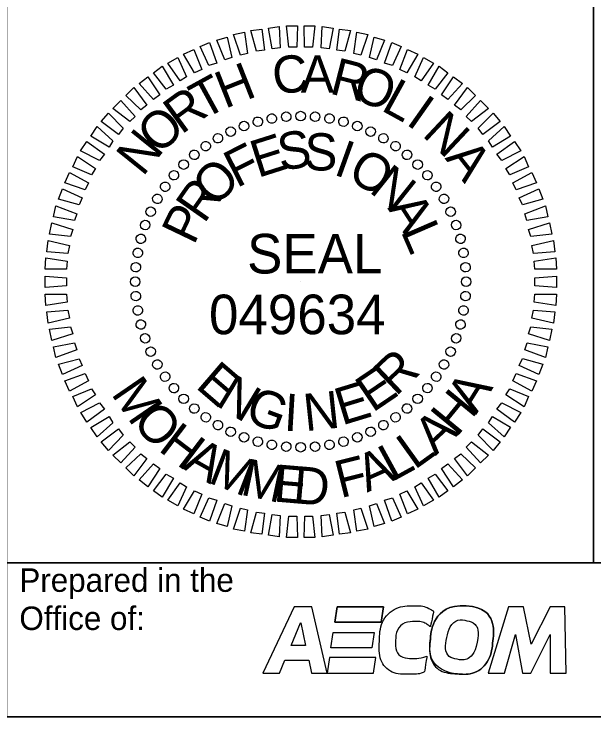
# Model space of a CAD drawing. Extents: x 270 to 1290, y -4845 to -4185.
# Drawn here: x 1150.7 to 1210, y -4305.5 to -4233.7 of the extents above; entities that cross this region are included whole.
import ezdxf

# ---------------------------------------------------------------- set-up
doc = ezdxf.new("R2010")
doc.units = 0
for name, color, linetype in [('Default', 7, 'Continuous'), ('Prop DSN Text', 7, 'Continuous'), ('Sheet Block Title CELL', 7, 'Continuous'), ('Sheet Border Standard 30in CELL', 7, 'Continuous'), ('Sheet Professional Seal CELL', 7, 'Continuous'), ('Sheet Sticker Exception Certification CELL', 7, 'Continuous')]:
    doc.layers.add(name, color=color, linetype=linetype)

# ---------------------------------------------------------------- blocks, each defined once
blk = doc.blocks.new('block 3')
at = {"layer": 'Default'}
blk.add_open_spline([(0.12275, 0.09393), (0.12554, 0.09373), (0.12726, 0.09146), (0.12695, 0.08843), (0.12663, 0.08531), (0.12411, 0.08298), (0.12127, 0.08318), (0.11848, 0.08338), (0.11676, 0.08565), (0.11707, 0.08868), (0.11739, 0.0918), (0.11991, 0.09413), (0.12275, 0.09393)], degree=3, dxfattribs=at)
blk = doc.blocks.new('block 2')
at = {"layer": 'Default'}
for p, q in [((0.10234, 0.09375), (0.10197, 0.09133)), ((0.10966, 0.09375), (0.10234, 0.09375)), ((0.10929, 0.09133), (0.10966, 0.09375)), ((0.10197, 0.09133), (0.10929, 0.09133)), ((0.10137, 0.08733), (0.10174, 0.08975)), ((0.10174, 0.08975), (0.10818, 0.08975)), ((0.10818, 0.08975), (0.10782, 0.08733)), ((0.10782, 0.08733), (0.10137, 0.08733)), ((0.10114, 0.08576), (0.10078, 0.08333)), ((0.10846, 0.08576), (0.10114, 0.08576)), ((0.1081, 0.08333), (0.10846, 0.08576)), ((0.10078, 0.08333), (0.1081, 0.08333))]:
    blk.add_line(p, q, dxfattribs=at)
for points in [[(0.10929, 0.09133), (0.10197, 0.09133), (0.10234, 0.09375), (0.10966, 0.09375), (0.10929, 0.09133)], [(0.10782, 0.08733), (0.10137, 0.08733), (0.10174, 0.08975), (0.10818, 0.08975), (0.10782, 0.08733)], [(0.10846, 0.08576), (0.10114, 0.08576), (0.10078, 0.08333), (0.1081, 0.08333), (0.10846, 0.08576)]]:
    blk.add_lwpolyline(points, dxfattribs=at)
blk = doc.blocks.new('POINT_DISPLAY')
at = {"layer": 'Default'}
blk.add_line((0, 0), (0, 0), dxfattribs=at)

msp = doc.modelspace()

# ---------------------------------------------------------------- linework, layer by layer
at = {"layer": 'Prop DSN Text'}
for p, q in [((1179.347, -4294.287), (1176.172, -4301.037)), ((1181.176, -4294.287), (1179.347, -4294.287)), ((1182.736, -4301.037), (1181.176, -4294.287)), ((1201.294, -4294.286), (1199.197, -4301.037)), ((1202.814, -4294.286), (1201.294, -4294.286)), ((1203.601, -4298.094), (1202.814, -4294.286)), ((1205.549, -4294.286), (1203.601, -4298.094)), ((1207.071, -4294.286), (1205.549, -4294.286)), ((1207.195, -4301.037), (1207.071, -4294.286)), ((1179.043, -4298.234), (1180.023, -4295.893)), ((1180.023, -4295.893), (1180.038, -4295.893)), ((1180.038, -4295.893), (1180.535, -4298.234)), ((1200.874, -4301.037), (1202.016, -4297.085)), ((1202.016, -4297.085), (1202.733, -4301.037)), ((1203.588, -4301.037), (1205.566, -4297.087)), ((1205.566, -4297.087), (1205.542, -4301.037)), ((1180.535, -4298.234), (1179.043, -4298.234)), ((1177.87, -4301.037), (1178.421, -4299.721)), ((1178.421, -4299.721), (1180.851, -4299.721)), ((1180.851, -4299.721), (1181.13, -4301.037)), ((1176.172, -4301.037), (1177.87, -4301.037)), ((1181.13, -4301.037), (1182.736, -4301.037)), ((1199.197, -4301.037), (1200.874, -4301.037)), ((1202.733, -4301.037), (1203.588, -4301.037)), ((1205.542, -4301.037), (1207.195, -4301.037))]:
    msp.add_line(p, q, dxfattribs=at)
for points in [[(1181.13, -4301.037), (1182.736, -4301.037), (1181.176, -4294.287), (1179.347, -4294.287), (1176.172, -4301.037), (1177.87, -4301.037), (1178.421, -4299.721), (1180.851, -4299.721), (1181.13, -4301.037)], [(1207.195, -4301.037), (1207.071, -4294.286), (1205.549, -4294.286), (1203.601, -4298.094), (1202.814, -4294.286), (1201.294, -4294.286), (1199.197, -4301.037), (1200.874, -4301.037), (1202.016, -4297.085), (1202.733, -4301.037), (1203.588, -4301.037), (1205.566, -4297.087), (1205.542, -4301.037), (1207.195, -4301.037)]]:
    msp.add_lwpolyline(points, dxfattribs=at)
for points in [[(1195.313, -4301.008), (1193.928, -4300.594), (1193.12, -4299.267), (1193.294, -4297.572), (1193.502, -4295.547), (1195.135, -4294.04), (1196.978, -4294.171)], [(1192.943, -4299.306), (1192.491, -4299.515), (1191.815, -4299.549), (1191.484, -4299.549), (1190.416, -4299.549), (1189.709, -4298.821), (1189.745, -4297.738), (1189.783, -4296.594), (1190.647, -4295.774), (1191.821, -4295.774), (1192.376, -4295.774), (1192.865, -4295.958), (1193.303, -4296.328), (1193.303, -4296.328), (1193.628, -4294.712), (1193.628, -4294.712), (1192.957, -4294.317), (1192.395, -4294.155), (1191.692, -4294.155), (1189.748, -4294.155), (1188.145, -4295.774), (1188.077, -4297.809), (1188.012, -4299.782), (1189.294, -4301.169), (1191.2, -4301.169), (1191.531, -4301.169), (1192.247, -4301.134), (1192.699, -4300.926), (1192.699, -4300.926), (1192.943, -4299.306), (1192.943, -4299.306)], [(1192.943, -4299.306), (1192.491, -4299.515), (1191.815, -4299.549), (1191.484, -4299.549), (1190.416, -4299.549), (1189.709, -4298.821), (1189.745, -4297.738), (1189.783, -4296.594), (1190.647, -4295.774), (1191.821, -4295.774), (1192.376, -4295.774), (1192.865, -4295.958), (1193.303, -4296.328), (1193.303, -4296.328), (1193.628, -4294.712), (1193.628, -4294.712), (1192.957, -4294.317), (1192.395, -4294.155), (1191.692, -4294.155), (1189.748, -4294.155), (1188.145, -4295.774), (1188.077, -4297.809), (1188.012, -4299.782), (1189.294, -4301.169), (1191.2, -4301.169), (1191.531, -4301.169), (1192.247, -4301.134), (1192.699, -4300.926), (1192.699, -4300.926), (1192.943, -4299.306), (1192.943, -4299.306)], [(1196.978, -4294.171), (1198.783, -4294.3), (1199.9, -4295.769), (1199.699, -4297.734), (1199.49, -4299.758), (1197.857, -4301.265), (1196.014, -4301.134), (1195.767, -4301.116), (1195.533, -4301.074), (1195.313, -4301.008)], [(1198.093, -4297.898), (1198.338, -4296.757), (1197.913, -4295.868), (1197.051, -4295.692), (1196.103, -4295.497), (1195.241, -4296.223), (1194.981, -4297.429), (1194.735, -4298.571), (1195.16, -4299.459), (1196.022, -4299.636), (1196.971, -4299.83), (1197.833, -4299.104), (1198.093, -4297.898)], [(1198.093, -4297.898), (1198.338, -4296.757), (1197.913, -4295.868), (1197.051, -4295.692), (1196.103, -4295.497), (1195.241, -4296.223), (1194.981, -4297.429), (1194.735, -4298.571), (1195.16, -4299.459), (1196.022, -4299.636), (1196.971, -4299.83), (1197.833, -4299.104), (1198.093, -4297.898)]]:
    msp.add_open_spline(points, degree=3, dxfattribs=at)
at = {"layer": 'Sheet Block Title CELL'}
msp.add_lwpolyline([(1149.97, -4289.78), (1269.971, -4289.78), (1269.971, -4305.529), (1149.97, -4305.529)], close=True, dxfattribs=at)
at = {"layer": 'Sheet Border Standard 30in CELL'}
for points in [[(1149.97, -4222.28), (1210, -4222.28), (1210, -4289.78), (1149.97, -4289.78)], [(1210, -4222.28), (1270.001, -4222.28), (1270.001, -4289.78), (1210, -4289.78)]]:
    msp.add_lwpolyline(points, close=True, dxfattribs=at)
at = {"layer": 'Sheet Professional Seal CELL'}
for points in [[(1175.506, -4237.468), (1174.932, -4235.342), (1176.047, -4235.207), (1176.317, -4237.368)], [(1177.126, -4237.232), (1176.722, -4235.105), (1177.836, -4234.937), (1177.937, -4237.131)], [(1178.814, -4237.063), (1178.579, -4234.869), (1179.692, -4234.869), (1179.625, -4237.063)], [(1180.435, -4237.063), (1180.368, -4234.869), (1181.481, -4234.869), (1181.245, -4237.063)], [(1182.123, -4237.131), (1182.224, -4234.937), (1183.338, -4235.105), (1182.933, -4237.232)], [(1183.743, -4237.367), (1184.013, -4235.206), (1185.127, -4235.342), (1184.552, -4237.468)], [(1173.886, -4237.874), (1173.143, -4235.747), (1174.291, -4235.511), (1174.594, -4237.705)], [(1185.464, -4237.705), (1185.769, -4235.511), (1186.915, -4235.747), (1186.174, -4237.874)], [(1170.646, -4238.92), (1169.734, -4236.962), (1170.712, -4236.557), (1171.455, -4238.684)], [(1172.266, -4238.347), (1171.455, -4236.321), (1172.503, -4236.017), (1172.974, -4238.11)], [(1187.084, -4238.11), (1187.557, -4236.017), (1188.603, -4236.321), (1187.794, -4238.347)], [(1188.603, -4238.684), (1189.346, -4236.557), (1190.326, -4236.962), (1189.414, -4238.92)], [(1169.16, -4239.663), (1168.046, -4237.773), (1169.092, -4237.3), (1169.903, -4239.325)], [(1190.157, -4239.325), (1190.966, -4237.3), (1192.013, -4237.773), (1190.9, -4239.663)], [(1167.709, -4240.473), (1166.426, -4238.684), (1167.472, -4238.11), (1168.35, -4240.068)], [(1191.709, -4240.068), (1192.588, -4238.11), (1193.634, -4238.684), (1192.351, -4240.473)], [(1166.258, -4241.351), (1164.974, -4239.663), (1165.852, -4238.988), (1166.999, -4240.945)], [(1193.06, -4240.945), (1194.208, -4238.987), (1195.085, -4239.662), (1193.802, -4241.35)], [(1164.974, -4242.398), (1163.489, -4240.776), (1164.401, -4240.068), (1165.616, -4241.925)], [(1194.444, -4241.925), (1195.659, -4240.068), (1196.571, -4240.776), (1195.085, -4242.398)], [(1163.658, -4243.444), (1162.139, -4241.993), (1162.948, -4241.182), (1164.299, -4242.971)], [(1195.76, -4242.97), (1197.11, -4241.182), (1197.921, -4241.992), (1196.402, -4243.443)], [(1162.545, -4244.658), (1160.822, -4243.308), (1161.633, -4242.499), (1163.084, -4244.119)], [(1196.976, -4244.119), (1198.427, -4242.499), (1199.237, -4243.308), (1197.516, -4244.658)], [(1161.396, -4245.975), (1159.607, -4244.658), (1160.35, -4243.781), (1161.869, -4245.334)], [(1198.191, -4245.333), (1199.71, -4243.781), (1200.453, -4244.658), (1198.664, -4245.975)], [(1160.417, -4247.258), (1158.56, -4246.144), (1159.202, -4245.165), (1160.822, -4246.617)], [(1199.237, -4246.617), (1200.858, -4245.164), (1201.499, -4246.144), (1199.642, -4247.258)], [(1159.439, -4248.643), (1157.514, -4247.663), (1158.156, -4246.684), (1159.945, -4248.001)], [(1200.115, -4248), (1201.904, -4246.684), (1202.546, -4247.663), (1200.622, -4248.642)], [(1158.628, -4250.094), (1156.704, -4249.283), (1157.177, -4248.237), (1159.033, -4249.452)], [(1201.027, -4249.452), (1202.884, -4248.237), (1203.355, -4249.283), (1201.431, -4250.094)], [(1157.987, -4251.646), (1155.894, -4250.904), (1156.366, -4249.857), (1158.325, -4250.903)], [(1201.735, -4250.903), (1203.693, -4249.857), (1204.166, -4250.903), (1202.073, -4251.646)], [(1157.345, -4253.165), (1155.252, -4252.591), (1155.658, -4251.545), (1157.683, -4252.457)], [(1202.377, -4252.457), (1204.403, -4251.545), (1204.807, -4252.591), (1202.715, -4253.165)], [(1156.872, -4254.785), (1154.746, -4254.381), (1154.982, -4253.266), (1157.109, -4254.077)], [(1202.95, -4254.077), (1205.078, -4253.266), (1205.313, -4254.381), (1203.186, -4254.785)], [(1156.468, -4256.407), (1154.341, -4256.17), (1154.577, -4255.022), (1156.704, -4255.697)], [(1203.355, -4255.697), (1205.482, -4255.022), (1205.718, -4256.17), (1203.592, -4256.407)], [(1156.197, -4258.128), (1154.038, -4257.959), (1154.172, -4256.811), (1156.366, -4257.317)], [(1203.693, -4257.317), (1205.887, -4256.811), (1206.023, -4257.959), (1203.862, -4258.127)], [(1156.063, -4259.748), (1153.869, -4259.748), (1153.937, -4258.601), (1156.131, -4258.938)], [(1203.93, -4258.938), (1206.124, -4258.601), (1206.191, -4259.748), (1203.997, -4259.748)], [(1156.063, -4261.436), (1153.869, -4261.604), (1153.869, -4260.458), (1156.063, -4260.626)], [(1203.997, -4260.626), (1206.191, -4260.457), (1206.192, -4261.604), (1203.997, -4261.435)], [(1156.131, -4263.123), (1153.937, -4263.461), (1153.869, -4262.314), (1156.063, -4262.314)], [(1203.997, -4262.314), (1206.191, -4262.314), (1206.124, -4263.461), (1203.93, -4263.123)], [(1156.366, -4264.744), (1154.172, -4265.25), (1154.038, -4264.103), (1156.197, -4263.934)], [(1203.862, -4263.934), (1206.023, -4264.102), (1205.887, -4265.25), (1203.693, -4264.743)], [(1156.704, -4266.365), (1154.577, -4267.04), (1154.341, -4265.892), (1156.468, -4265.655)], [(1203.592, -4265.655), (1205.718, -4265.891), (1205.482, -4267.04), (1203.356, -4266.364)], [(1157.109, -4267.985), (1154.983, -4268.794), (1154.746, -4267.681), (1156.872, -4267.275)], [(1203.187, -4267.275), (1205.313, -4267.68), (1205.078, -4268.794), (1202.95, -4267.985)], [(1157.683, -4269.605), (1155.658, -4270.517), (1155.252, -4269.469), (1157.346, -4268.897)], [(1202.715, -4268.896), (1204.807, -4269.469), (1204.403, -4270.516), (1202.377, -4269.605)], [(1158.325, -4271.157), (1156.366, -4272.205), (1155.894, -4271.157), (1157.987, -4270.416)], [(1202.073, -4270.415), (1204.166, -4271.157), (1203.693, -4272.204), (1201.735, -4271.157)], [(1159.034, -4272.61), (1157.177, -4273.825), (1156.704, -4272.779), (1158.628, -4271.968)], [(1201.431, -4271.968), (1203.355, -4272.778), (1202.884, -4273.824), (1201.027, -4272.61)], [(1159.945, -4274.061), (1158.156, -4275.377), (1157.515, -4274.399), (1159.439, -4273.419)], [(1200.622, -4273.419), (1202.546, -4274.398), (1201.904, -4275.377), (1200.115, -4274.061)], [(1160.822, -4275.445), (1159.202, -4276.896), (1158.56, -4275.918), (1160.417, -4274.804)], [(1199.642, -4274.804), (1201.499, -4275.917), (1200.858, -4276.896), (1199.237, -4275.444)], [(1161.87, -4276.727), (1160.35, -4278.281), (1159.608, -4277.402), (1161.397, -4276.087)], [(1198.664, -4276.086), (1200.453, -4277.402), (1199.71, -4278.28), (1198.191, -4276.727)], [(1163.084, -4277.943), (1161.633, -4279.563), (1160.822, -4278.752), (1162.545, -4277.402)], [(1197.516, -4277.402), (1199.237, -4278.752), (1198.428, -4279.563), (1196.976, -4277.943)], [(1164.299, -4279.09), (1162.949, -4280.88), (1162.139, -4280.069), (1163.658, -4278.618)], [(1196.402, -4278.618), (1197.921, -4280.069), (1197.111, -4280.88), (1195.76, -4279.09)], [(1165.616, -4280.137), (1164.401, -4281.994), (1163.49, -4281.284), (1164.974, -4279.664)], [(1195.085, -4279.664), (1196.571, -4281.284), (1195.659, -4281.994), (1194.445, -4280.137)], [(1167, -4281.115), (1165.853, -4283.074), (1164.974, -4282.399), (1166.258, -4280.711)], [(1193.803, -4280.711), (1195.085, -4282.399), (1194.208, -4283.074), (1193.06, -4281.115)], [(1168.35, -4281.994), (1167.473, -4283.951), (1166.427, -4283.377), (1167.709, -4281.588)], [(1192.351, -4281.588), (1193.634, -4283.377), (1192.588, -4283.951), (1191.709, -4281.994)], [(1169.903, -4282.737), (1169.093, -4284.762), (1168.047, -4284.289), (1169.16, -4282.399)], [(1190.9, -4282.399), (1192.014, -4284.289), (1190.967, -4284.762), (1190.157, -4282.736)], [(1171.456, -4283.377), (1170.713, -4285.504), (1169.735, -4285.1), (1170.646, -4283.141)], [(1189.414, -4283.141), (1190.326, -4285.1), (1189.347, -4285.504), (1188.604, -4283.377)], [(1172.975, -4283.951), (1172.503, -4286.045), (1171.456, -4285.74), (1172.266, -4283.715)], [(1187.794, -4283.715), (1188.604, -4285.74), (1187.558, -4286.045), (1187.085, -4283.951)], [(1174.595, -4284.357), (1174.292, -4286.551), (1173.143, -4286.314), (1173.886, -4284.188)], [(1176.317, -4284.694), (1176.047, -4286.854), (1174.932, -4286.72), (1175.507, -4284.593)], [(1184.553, -4284.593), (1185.127, -4286.72), (1184.013, -4286.854), (1183.744, -4284.694)], [(1186.174, -4284.188), (1186.916, -4286.314), (1185.769, -4286.551), (1185.464, -4284.357)], [(1177.937, -4284.931), (1177.836, -4287.125), (1176.722, -4286.956), (1177.126, -4284.829)], [(1179.625, -4284.997), (1179.693, -4287.191), (1178.579, -4287.191), (1178.814, -4284.997)], [(1181.245, -4284.997), (1181.482, -4287.191), (1180.368, -4287.191), (1180.436, -4284.997)], [(1182.933, -4284.828), (1183.338, -4286.956), (1182.225, -4287.125), (1182.124, -4284.931)]]:
    msp.add_lwpolyline(points, close=True, dxfattribs=at)
for centre, major_axis in [((1177.086, -4244.35), (-0.084, 0.479)), ((1178.55, -4244.157), (-0.042, 0.484)), ((1180.026, -4244.092), (0, 0.486)), ((1181.502, -4244.157), (0.042, 0.484)), ((1182.966, -4244.35), (0.084, 0.479)), ((1175.643, -4244.669), (-0.126, 0.47)), ((1184.408, -4244.669), (0.126, 0.47)), ((1172.87, -4245.679), (-0.205, 0.441)), ((1174.235, -4245.114), (-0.166, 0.457)), ((1185.817, -4245.114), (0.166, 0.457)), ((1187.182, -4245.679), (0.205, 0.441)), ((1171.56, -4246.361), (-0.243, 0.421)), ((1188.492, -4246.361), (0.243, 0.421)), ((1170.314, -4247.155), (-0.279, 0.398)), ((1189.738, -4247.154), (0.279, 0.398)), ((1169.142, -4248.054), (-0.312, 0.372)), ((1190.91, -4248.054), (0.312, 0.372)), ((1168.053, -4249.052), (-0.344, 0.344)), ((1191.999, -4249.052), (0.344, 0.344)), ((1167.055, -4250.141), (-0.372, 0.312)), ((1192.997, -4250.141), (0.372, 0.312)), ((1166.156, -4251.313), (-0.398, 0.279)), ((1193.896, -4251.313), (0.398, 0.279)), ((1165.362, -4252.559), (-0.421, 0.243)), ((1194.69, -4252.558), (0.421, 0.243)), ((1164.68, -4253.869), (-0.441, 0.205)), ((1195.372, -4253.869), (0.441, 0.205)), ((1164.115, -4255.234), (-0.457, 0.166)), ((1195.937, -4255.233), (0.457, 0.166)), ((1163.671, -4256.642), (-0.47, 0.126)), ((1196.381, -4256.642), (0.47, 0.126)), ((1163.351, -4258.085), (-0.479, 0.084)), ((1196.701, -4258.084), (0.479, 0.084)), ((1163.158, -4259.549), (-0.484, 0.042)), ((1196.894, -4259.549), (0.484, 0.042)), ((1163.094, -4261.025), (-0.486, 0)), ((1196.958, -4261.025), (0.486, 0)), ((1163.158, -4262.501), (-0.484, -0.042)), ((1196.894, -4262.5), (0.484, -0.042)), ((1163.351, -4263.965), (-0.479, -0.084)), ((1196.701, -4263.965), (0.479, -0.084)), ((1163.671, -4265.407), (-0.47, -0.126)), ((1196.381, -4265.407), (0.47, -0.126)), ((1164.115, -4266.816), (-0.457, -0.166)), ((1195.937, -4266.816), (0.457, -0.166)), ((1164.68, -4268.181), (-0.441, -0.205)), ((1195.372, -4268.18), (0.441, -0.205)), ((1165.362, -4269.491), (-0.421, -0.243)), ((1194.69, -4269.491), (0.421, -0.243)), ((1166.156, -4270.737), (-0.398, -0.279)), ((1193.896, -4270.736), (0.398, -0.279)), ((1167.055, -4271.909), (-0.372, -0.312)), ((1192.997, -4271.908), (0.372, -0.312)), ((1168.053, -4272.998), (-0.344, -0.344)), ((1191.999, -4272.997), (0.344, -0.344)), ((1169.142, -4273.996), (-0.312, -0.372)), ((1190.91, -4273.995), (0.312, -0.372)), ((1170.314, -4274.895), (-0.279, -0.398)), ((1189.738, -4274.895), (0.279, -0.398)), ((1171.56, -4275.688), (-0.243, -0.421)), ((1188.492, -4275.688), (0.243, -0.421)), ((1172.87, -4276.371), (-0.205, -0.441)), ((1187.182, -4276.37), (0.205, -0.441)), ((1174.235, -4276.936), (-0.166, -0.457)), ((1175.644, -4277.38), (-0.126, -0.47)), ((1184.408, -4277.38), (0.126, -0.47)), ((1185.817, -4276.936), (0.166, -0.457)), ((1177.086, -4277.7), (-0.084, -0.479)), ((1178.55, -4277.892), (-0.042, -0.484)), ((1180.026, -4277.957), (0, -0.486)), ((1181.502, -4277.892), (0.042, -0.484)), ((1182.966, -4277.7), (0.084, -0.479))]:
    msp.add_ellipse(centre, major_axis=major_axis, ratio=0.999708, dxfattribs=at)
at = {"layer": 'Sheet Sticker Exception Certification CELL'}
msp.add_line((1149.97, -4305.529), (1269.993, -4305.529), dxfattribs=at)

# ---------------------------------------------------------------- block references
at = {"layer": 'Prop DSN Text', "xscale": 648.001866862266, "yscale": 648.0018668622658, "rotation": 1.3379890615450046e-09}
for name in ['block 3', 'block 2']:
    msp.add_blockref(name, (1117.433, -4355.037), dxfattribs=at)
at = {"layer": 'Sheet Professional Seal CELL', "xscale": 41.411959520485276, "yscale": 41.41195952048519, "rotation": 0.00042986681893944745}
for p in [(1177.093, -4244.355), (1178.544, -4244.152), (1180.03, -4244.085), (1181.515, -4244.152), (1182.967, -4244.355), (1174.224, -4245.098), (1175.642, -4244.658), (1184.418, -4244.658), (1185.836, -4245.098), (1172.874, -4245.671), (1187.187, -4245.671), (1171.556, -4246.346), (1188.502, -4246.346), (1170.308, -4247.157), (1189.752, -4247.157), (1169.127, -4248.034), (1190.933, -4248.034), (1168.047, -4249.047), (1192.014, -4249.047), (1167.034, -4250.127), (1193.026, -4250.127), (1166.155, -4251.309), (1193.903, -4251.309), (1165.346, -4252.558), (1194.714, -4252.558), (1164.671, -4253.875), (1195.389, -4253.875), (1164.097, -4255.225), (1195.963, -4255.225), (1163.658, -4256.642), (1196.402, -4256.642), (1163.354, -4258.095), (1163.152, -4259.546), (1196.908, -4259.546), (1163.084, -4261.03), (1180.03, -4261.03), (1196.976, -4261.03), (1163.152, -4262.516), (1196.908, -4262.516), (1163.354, -4263.968), (1196.705, -4263.967), (1163.658, -4265.419), (1196.402, -4265.418), (1164.097, -4266.837), (1195.964, -4266.836), (1195.389, -4268.187), (1194.714, -4269.504), (1166.156, -4270.753), (1193.904, -4270.753), (1167.034, -4271.935), (1193.026, -4271.935), (1168.047, -4273.014), (1192.014, -4273.014), (1169.127, -4274.027), (1190.933, -4274.026), (1170.309, -4274.905), (1189.752, -4274.905), (1171.557, -4275.714), (1188.503, -4275.714), (1172.874, -4276.389), (1187.187, -4276.389), (1174.224, -4276.964), (1175.642, -4277.402), (1184.418, -4277.402), (1185.837, -4276.964), (1177.093, -4277.706), (1178.544, -4277.908), (1180.03, -4277.976), (1181.515, -4277.908), (1182.967, -4277.706)]:
    msp.add_blockref('POINT_DISPLAY', p, dxfattribs=at)

# ---------------------------------------------------------------- texts
at = {"layer": 'Prop DSN Text'}
for s, height, p in [('Prepared in the ', 2.40001, (1151.243, -4292.74)), ('Office of:', 2.4, (1151.243, -4296.64))]:
    msp.add_text(s, height=height, rotation=0, dxfattribs=at).set_placement(p)
at = {"layer": 'Sheet Professional Seal CELL'}
for s, height, rotation, p in [('C', 3.806, 7.2203, (1177.37, -4241.924)), ('A', 3.806, 0.02075, (1180.039, -4241.688)), ('H', 3.806, 21.61991, (1172.267, -4243.376)), ('R', 3.806, 345.62153, (1182.871, -4241.758)), ('O', 3.806, 338.42159, (1185.136, -4242.233)), ('T', 3.806, 28.8202, (1170.074, -4244.523)), ('L', 3.806, 331.2213, (1188.138, -4243.447)), ('R', 3.806, 36.02094, (1167.815, -4246.04)), ('I', 3.806, 324.781, (1190.69, -4244.856)), ('O', 3.806, 43.22217, (1165.522, -4248.163)), ('N', 3.806, 316.81934, (1192.354, -4246.046)), ('N', 3.806, 51.1609, (1163.86, -4250.366)), ('E', 3.807, 17.6115, (1175.639, -4250.433)), ('S', 3.807, 8.25604, (1177.937, -4249.689)), ('S', 3.807, 358.90083, (1180.368, -4249.621)), ('I', 3.807, 340.19003, (1183.275, -4250.028)), ('F', 3.807, 26.96746, (1173.478, -4251.479)), ('A', 3.806, 308.06255, (1194.73, -4248.402)), ('O', 3.807, 330.83391, (1184.663, -4250.504)), ('O', 3.807, 45.68167, (1171.293, -4253.496)), ('N', 3.807, 321.47704, (1186.919, -4251.784)), ('R', 3.807, 55.04008, (1170.143, -4255.186)), ('P', 3.807, 64.39932, (1169.095, -4257.38)), ('A', 3.807, 302.7607, (1188.879, -4253.51)), ('L', 3.807, 293.40128, (1190.228, -4255.84)), ('SEAL', 4.0496, 0.00043, (1174.543, -4260.186)), ('049634', 4.0508, 0.00043, (1170.645, -4266.398)), ('R', 3.807, 43.48184, (1189.756, -4272.84)), ('E', 3.807, 319.27732, (1169.157, -4271.797)), ('E', 3.807, 34.12452, (1187.386, -4274.468)), ('M', 3.807, 304.41113, (1160.563, -4272.474)), ('N', 3.807, 328.63439, (1171.189, -4273.59)), ('A', 3.807, 57.87872, (1197.976, -4274.687)), ('E', 3.807, 16.96729, (1184.242, -4275.742)), ('G', 3.807, 339.50364, (1174.159, -4275.2)), ('I', 3.807, 356.70163, (1178.246, -4276.256)), ('N', 3.807, 6.05682, (1180.506, -4276.323)), ('H', 3.807, 50.68353, (1196.019, -4276.956)), ('O', 3.807, 313.50721, (1162.676, -4275.506)), ('A', 3.807, 42.87926, (1193.829, -4278.869)), ('H', 3.807, 322.66556, (1165.349, -4278.231)), ('L', 3.807, 35.69399, (1191.68, -4280.32)), ('A', 3.807, 330.54958, (1167.863, -4280.104)), ('M', 3.807, 338.92584, (1170.43, -4281.524)), ('A', 3.807, 23.98385, (1186.819, -4282.6)), ('L', 3.807, 28.72874, (1189.42, -4281.502)), ('F', 3.807, 14.0832, (1184.099, -4283.177)), ('M', 3.807, 348.01683, (1173.755, -4282.78)), ('E', 3.807, 355.14349, (1177.177, -4283.489)), ('D', 3.807, 355.14349, (1179.167, -4283.653))]:
    msp.add_text(s, height=height, rotation=rotation, dxfattribs=at).set_placement(p)

doc.saveas('drawing.dxf')
